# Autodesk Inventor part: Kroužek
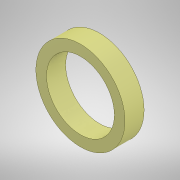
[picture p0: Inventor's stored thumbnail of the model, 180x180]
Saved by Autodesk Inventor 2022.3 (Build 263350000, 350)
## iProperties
Created: 2024-12
Part Number: Kroužek
Material: Všeobecné
Document SubType Name: Modeling
Designer: Hra42
Density: 1 g/cm^3
Appearance: Výchozí
Author: Hra42
Sending System: SolidWorks 2012
Last Author: Hra42
Last Saved: 2025-11-10
Source: vymezovací kroužek
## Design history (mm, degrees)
node "Vymezovací kroužek_Solid.SLDPRT"
node "Těleso1"
feature "Importovaný1"
